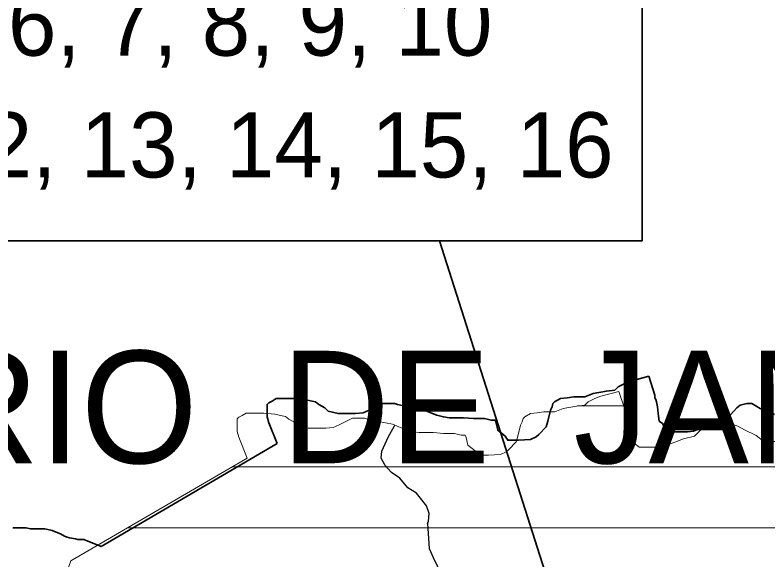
# Model space of a CAD drawing. Extents: x -10.5 to 30.8, y 18.4 to 58.7.
# Drawn here: x -1.163 to 1.312, y 42.173 to 43.963 of the extents above; entities that cross this region are included whole.
import ezdxf
from ezdxf.enums import TextEntityAlignment as Align

# ---------------------------------------------------------------- set-up
doc = ezdxf.new("R2010")
doc.units = 0
doc.header["$LTSCALE"] = 0.08
for name, color, linetype, lineweight in [('43', 7, 'Continuous', 13), ('48', 7, 'Continuous', 35), ('51', 7, 'Continuous', 35), ('9', 7, 'Continuous', 25)]:
    doc.layers.add(name, color=color, linetype=linetype, lineweight=lineweight)
doc.layers.add('56', color=7, linetype='Continuous')

msp = doc.modelspace()

# ---------------------------------------------------------------- linework, layer by layer
at = {"layer": '43'}
for p, q in [((0.68602, 42.67876), (0.8374, 42.67876)), ((0.68602, 42.67876), (0.8374, 42.67876)), ((-0.44965, 42.47876), (2.07573, 42.47876)), ((-0.44965, 42.47876), (2.07573, 42.47876)), ((-0.79299, 42.27876), (2.11235, 42.27876)), ((-0.79299, 42.27876), (2.11235, 42.27876))]:
    msp.add_line(p, q, dxfattribs=at)
for points in [[(0.82196, 42.72664), (0.76238, 42.71119), (0.74313, 42.703), (0.72112, 42.69207), (0.71011, 42.68113), (0.68261, 42.67843), (0.63862, 42.67027), (0.61662, 42.66208), (0.61112, 42.65935), (0.57539, 42.6594), (0.55339, 42.65669), (0.5314, 42.65398), (0.51214, 42.64305), (0.50663, 42.63757), (0.50387, 42.62662), (0.49834, 42.61567), (0.49003, 42.58006), (0.48451, 42.56089), (0.45973, 42.53626), (0.45146, 42.52806), (0.43221, 42.51986), (0.39373, 42.51718), (0.37449, 42.51721), (0.358, 42.51723), (0.34978, 42.53094), (0.32507, 42.55015), (0.31962, 42.57482), (0.31688, 42.58304), (0.30315, 42.58306), (0.28117, 42.58857), (0.24544, 42.58862), (0.21246, 42.59141), (0.18772, 42.59144), (0.16573, 42.59147), (0.1465, 42.59424), (0.12452, 42.59975), (0.07783, 42.619), (0.03112, 42.62728), (-0.00459, 42.63555), (-0.01283, 42.6383), (-0.02108, 42.63832), (-0.05406, 42.63836), (-0.09808, 42.61651), (-0.11733, 42.60831), (-0.14207, 42.60561), (-0.1778, 42.60566), (-0.19979, 42.60569), (-0.23276, 42.61395), (-0.24373, 42.62493), (-0.26295, 42.63592), (-0.27394, 42.64415), (-0.28492, 42.64691), (-0.30965, 42.65242), (-0.34538, 42.65521), (-0.36736, 42.65524), (-0.40309, 42.65529), (-0.41685, 42.64709), (-0.42785, 42.64163), (-0.43336, 42.63616), (-0.43339, 42.61972), (-0.43343, 42.59506), (-0.42797, 42.57587), (-0.40061, 42.50733)], [(0.82196, 42.72664), (0.76238, 42.71119), (0.74313, 42.703), (0.72112, 42.69207), (0.71011, 42.68113), (0.68261, 42.67843), (0.63862, 42.67027), (0.61662, 42.66208), (0.61112, 42.65935), (0.57539, 42.6594), (0.55339, 42.65669), (0.5314, 42.65398), (0.51214, 42.64305), (0.50663, 42.63757), (0.50387, 42.62662), (0.49834, 42.61567), (0.49003, 42.58006), (0.48451, 42.56089), (0.45973, 42.53626), (0.45146, 42.52806), (0.43221, 42.51986), (0.39373, 42.51718), (0.37449, 42.51721), (0.358, 42.51723), (0.34978, 42.53094), (0.32507, 42.55015), (0.31962, 42.57482), (0.31688, 42.58304), (0.30315, 42.58306), (0.28117, 42.58857), (0.24544, 42.58862), (0.21246, 42.59141), (0.18772, 42.59144), (0.16573, 42.59147), (0.1465, 42.59424), (0.12452, 42.59975), (0.07783, 42.619), (0.03112, 42.62728), (-0.00459, 42.63555), (-0.01283, 42.6383), (-0.02108, 42.63832), (-0.05406, 42.63836), (-0.09808, 42.61651), (-0.11733, 42.60831), (-0.14207, 42.60561), (-0.1778, 42.60566), (-0.19979, 42.60569), (-0.23276, 42.61395), (-0.24373, 42.62493), (-0.26295, 42.63592), (-0.27394, 42.64415), (-0.28492, 42.64691), (-0.30965, 42.65242), (-0.34538, 42.65521), (-0.36736, 42.65524), (-0.40309, 42.65529), (-0.41685, 42.64709), (-0.42785, 42.64163), (-0.43336, 42.63616), (-0.43339, 42.61972), (-0.43343, 42.59506), (-0.42797, 42.57587), (-0.40061, 42.50733)], [(1.11917, 42.62891), (1.11128, 42.62303), (1.08924, 42.5984), (1.06997, 42.57925), (1.03422, 42.57108), (1.01497, 42.56288), (0.97647, 42.54924), (0.96822, 42.54651), (0.94898, 42.5438), (0.92698, 42.54383), (0.91599, 42.54384), (0.91049, 42.54385), (0.88851, 42.54388), (0.87753, 42.55212), (0.86657, 42.57131), (0.85559, 42.57955), (0.85288, 42.60421), (0.85018, 42.62613), (0.84746, 42.64258), (0.84472, 42.6508), (0.84199, 42.65628), (0.842, 42.6645), (0.82196, 42.72664)], [(1.11917, 42.62891), (1.11128, 42.62303), (1.08924, 42.5984), (1.06997, 42.57925), (1.03422, 42.57108), (1.01497, 42.56288), (0.97647, 42.54924), (0.96822, 42.54651), (0.94898, 42.5438), (0.92698, 42.54383), (0.91599, 42.54384), (0.91049, 42.54385), (0.88851, 42.54388), (0.87753, 42.55212), (0.86657, 42.57131), (0.85559, 42.57955), (0.85288, 42.60421), (0.85018, 42.62613), (0.84746, 42.64258), (0.84472, 42.6508), (0.84199, 42.65628), (0.842, 42.6645), (0.82196, 42.72664)], [(1.44204, 42.63718), (1.38347, 42.67197), (1.38345, 42.66101), (1.38343, 42.65005), (1.3779, 42.63087), (1.37514, 42.62266), (1.35308, 42.58159), (1.34205, 42.56243), (1.32006, 42.56246), (1.29807, 42.56249), (1.27337, 42.5817), (1.23493, 42.60094), (1.21295, 42.61193), (1.18823, 42.62018), (1.16731, 42.63274), (1.16731, 42.63274), (1.11917, 42.62891)], [(1.44204, 42.63718), (1.38347, 42.67197), (1.38345, 42.66101), (1.38343, 42.65005), (1.3779, 42.63087), (1.37514, 42.62266), (1.35308, 42.58159), (1.34205, 42.56243), (1.32006, 42.56246), (1.29807, 42.56249), (1.27337, 42.5817), (1.23493, 42.60094), (1.21295, 42.61193), (1.18823, 42.62018), (1.16731, 42.63274), (1.16731, 42.63274), (1.11917, 42.62891)], [(-0.40061, 42.50733), (-0.97933, 42.17022), (-1.05525, 41.95433)], [(-0.40061, 42.50733), (-0.97933, 42.17022), (-1.05525, 41.95433)]]:
    msp.add_lwpolyline(points, dxfattribs=at)
at = {"layer": '48'}
msp.add_line((-0.30196, 42.55523), (-0.88022, 42.21732), dxfattribs=at)
for points in [[(0.92031, 42.77621), (0.86074, 42.76069), (0.8415, 42.75247), (0.81951, 42.74151), (0.80851, 42.73055), (0.78102, 42.72781), (0.73704, 42.71959), (0.71505, 42.71137), (0.70955, 42.70863), (0.67382, 42.70864), (0.65183, 42.7059), (0.62985, 42.70316), (0.6106, 42.6922), (0.6051, 42.68672), (0.60235, 42.67576), (0.59684, 42.6648), (0.58858, 42.62918), (0.58308, 42.61), (0.55833, 42.58534), (0.55008, 42.57712), (0.53084, 42.5689), (0.49236, 42.56617), (0.47312, 42.56617), (0.45663, 42.56617), (0.44839, 42.57987), (0.42366, 42.59905), (0.41817, 42.62371), (0.41543, 42.63192), (0.40169, 42.63193), (0.3797, 42.63741), (0.34397, 42.63741), (0.31099, 42.64015), (0.28625, 42.64015), (0.26426, 42.64015), (0.24502, 42.64289), (0.22304, 42.64837), (0.17632, 42.66755), (0.1296, 42.67577), (0.09388, 42.68399), (0.08563, 42.68673), (0.07739, 42.68673), (0.04441, 42.68674), (0.00042, 42.66482), (-0.01882, 42.6566), (-0.04356, 42.65386), (-0.07929, 42.65386), (-0.10128, 42.65386), (-0.13426, 42.66208), (-0.14525, 42.67304), (-0.16449, 42.684), (-0.17548, 42.69222), (-0.18647, 42.69496), (-0.2112, 42.70044), (-0.24693, 42.70318), (-0.26892, 42.70319), (-0.30465, 42.70319), (-0.3184, 42.69497), (-0.32939, 42.68949), (-0.33489, 42.68401), (-0.3349, 42.66757), (-0.33491, 42.64291), (-0.32942, 42.62373), (-0.30196, 42.55523)], [(1.33344, 42.65108), (1.31145, 42.66204), (1.28672, 42.67026), (1.25924, 42.6867), (1.24275, 42.6867), (1.22076, 42.68122), (1.20976, 42.673), (1.18776, 42.64834), (1.16852, 42.62916), (1.13278, 42.62095), (1.11354, 42.61273), (1.07506, 42.59903), (1.06681, 42.59629), (1.04757, 42.59355), (1.02558, 42.59355), (1.01459, 42.59355), (1.00909, 42.59355), (0.9871, 42.59355), (0.97611, 42.60177), (0.96513, 42.62095), (0.95414, 42.62917), (0.95139, 42.65383), (0.94866, 42.67575), (0.94592, 42.69219), (0.94317, 42.70041), (0.94043, 42.70589), (0.94043, 42.71411), (0.92031, 42.77621)], [(-0.88022, 42.21732), (-0.93701, 42.24015), (-0.94251, 42.24015), (-0.95075, 42.24015), (-0.95625, 42.24015), (-0.96449, 42.24289), (-0.98373, 42.24564), (-0.99197, 42.24838), (-1.00022, 42.25112), (-1.01396, 42.25934), (-1.0222, 42.26208), (-1.04144, 42.2703), (-1.05518, 42.27304), (-1.06618, 42.27578), (-1.07442, 42.27578), (-1.09366, 42.27578), (-1.1129, 42.27578), (-1.12664, 42.27852), (-1.14588, 42.27852), (-1.15687, 42.27852), (-1.16237, 42.27852), (-1.17061, 42.27852)]]:
    msp.add_lwpolyline(points, dxfattribs=at)
at = {"layer": '51'}
msp.add_line((0.23174, 43.22066), (3.42713, 33.21789), dxfattribs=at)
msp.add_lwpolyline([(-1.9563, 43.22066), (0.89782, 43.22066), (0.89782, 44.23436), (-1.9563, 44.23436)], close=True, dxfattribs=at)
at = {"layer": '9'}
for points in [[(0.19228, 42.29257), (0.19579, 42.30098), (0.19772, 42.32606), (0.18961, 42.3509), (0.17412, 42.37055), (0.15605, 42.39264), (0.12806, 42.40949), (0.10223, 42.44141), (0.07419, 42.46076), (0.05362, 42.4828), (0.04051, 42.50751), (0.04249, 42.53009), (0.06396, 42.57816), (0.08326, 42.61116), (0.08578, 42.61572)], [(0.19228, 42.29257), (0.19787, 42.21092), (0.2111, 42.1812), (0.22428, 42.15399), (0.23482, 42.13171), (0.25032, 42.11206), (0.26333, 42.09235), (0.27382, 42.07257), (0.28448, 42.0453), (0.29509, 42.02052), (0.29805, 42.00057), (0.30144, 41.9631), (0.3023, 41.92558), (0.30059, 41.89049), (0.30135, 41.85797), (0.29959, 41.82539), (0.29795, 41.7878), (0.29621, 41.75523), (0.2945, 41.72014), (0.28756, 41.69494), (0.28078, 41.66224), (0.26249, 41.57413)]]:
    msp.add_lwpolyline(points, dxfattribs=at)

# ---------------------------------------------------------------- texts
at = {"layer": '51'}
for s, p in [('5, 6, 7, 8, 9, 10', (-0.54942, 43.82928)), ('11, 12, 13, 14, 15, 16', (-0.54942, 43.42921))]:
    msp.add_text(s, height=0.2142, dxfattribs=at).set_placement(p, align=Align.CENTER)
at = {"layer": '56'}
msp.add_text('RIO  DE  JANEIRO', height=0.3694, dxfattribs=at).set_placement((-1.44084, 42.49068))

doc.saveas('drawing.dxf')
